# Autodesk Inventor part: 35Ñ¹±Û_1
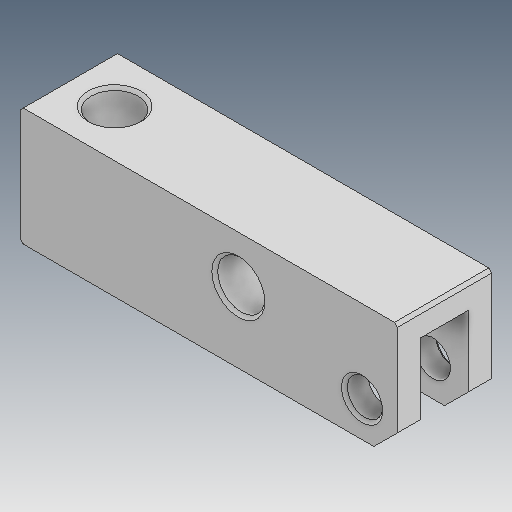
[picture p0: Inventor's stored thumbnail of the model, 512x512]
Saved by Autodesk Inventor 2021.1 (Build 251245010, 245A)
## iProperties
Created: 2019-04
Part Number: 35Ñ¹±Û_1
Material: Ogólny
Document SubType Name: Modeling
Designer: user
Density: 1 g/cm^3
Appearance: Domyślna
Author: user
Revision Number: ÈÎºÎ
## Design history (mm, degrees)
feature "ÊäÈë1"
node "Bryła1"
